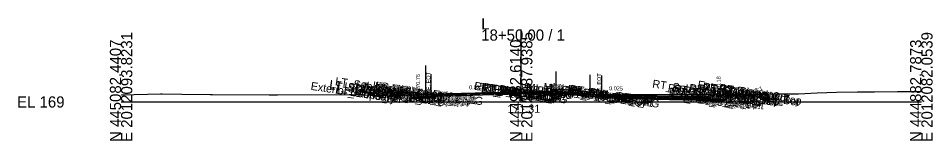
# Model space of a CAD drawing. Extents: x -26 to 4203, y -10 to 9526.
# Drawn here: x -25.7 to 202.8, y 8490.3 to 8520.9 of the extents above; entities that cross this region are included whole.
import ezdxf

# ---------------------------------------------------------------- set-up
doc = ezdxf.new("R2010")
doc.units = 0
for name, color, linetype in [('Default', 7, 'Continuous'), ('Exist CMT Pavement', 7, 'Continuous'), ('Exist Cross Section Cell', 7, 'Continuous'), ('Exist XS Center Line Elevation Label', 7, 'Continuous'), ('Exist XS Ground Line', 7, 'Continuous'), ('Prop CMT Conc Surface', 7, 'Continuous'), ('Prop CMT Concrete Structures', 7, 'Continuous'), ('Prop CMT Pvmt Course 1', 7, 'Continuous'), ('Prop CMT Pvmt Course 1 CG', 7, 'Continuous'), ('Prop CMT Pvmt Course 1 Wedge', 7, 'Continuous'), ('Prop CMT Pvmt Course 2', 7, 'Continuous'), ('Prop CMT Pvmt Course 2 Wedge', 7, 'Continuous'), ('Prop CMT Pvmt Course 3', 7, 'Continuous'), ('Prop CMT Pvmt Course 3 Wedge', 7, 'Continuous'), ('Prop CMT Pvmt Surface', 7, 'Continuous'), ('Prop CMT Pvmt Wedge Surface 1', 7, 'Continuous'), ('Prop CMT Pvmt Wedge Surface 2', 7, 'Continuous'), ('Prop CMT Pvmt Wedge Surface 3', 7, 'Continuous'), ('Prop CMT Slope Grass', 7, 'Continuous'), ('Prop CMT Subgrade Earthwork', 7, 'Continuous'), ('Prop XS Hydro Elevations', 7, 'Continuous'), ('Prop XS Label Text', 7, 'Continuous'), ('Prop XS SE Text', 7, 'Continuous'), ('Prop XS Side Slope Text', 7, 'Continuous'), ('Scratch_Level_0', 7, 'Continuous'), ('Scratch_Level_3', 7, 'Continuous')]:
    doc.layers.add(name, color=color, linetype=linetype)

msp = doc.modelspace()

# ---------------------------------------------------------------- linework, layer by layer
at = {"layer": 'Exist CMT Pavement'}
for points in [[(100, 8502.3), (98.56, 8502.3), (97.56, 8502.29), (96.44, 8502.29), (95.06, 8502.29), (93.77, 8502.28), (92.56, 8502.27), (91.48, 8502.25), (90.05, 8502.22), (88.47, 8502.17), (87.56, 8502.15), (86.74, 8502.12), (85, 8502.07), (83.11, 8502.02), (82.51, 8502), (80.47, 8501.95), (80.04, 8501.94), (78.58, 8501.94)], [(100, 8502.3), (100.07, 8502.31), (100.94, 8502.3), (102.56, 8502.28), (104.39, 8502.25), (105.05, 8502.24), (107.05, 8502.21), (107.55, 8502.2), (108, 8502.18), (110.06, 8502.13), (112.39, 8502.01), (112.57, 8502.01), (112.73, 8502), (115.08, 8501.88), (115.56, 8501.85), (117.58, 8501.76), (119.84, 8501.62), (120.06, 8501.61)]]:
    msp.add_lwpolyline(points, dxfattribs=at)
at = {"layer": 'Exist Cross Section Cell'}
for p, q in [((100, 8500), (100, 8518.13)), ((0, 8500), (100, 8500)), ((100, 8500), (200, 8500))]:
    msp.add_line(p, q, dxfattribs=at)
at = {"layer": 'Exist XS Ground Line'}
msp.add_lwpolyline([(0, 8501.79), (9.83, 8502.01), (10.23, 8502.02), (15.2, 8501.97), (22.3, 8501.85), (22.81, 8501.85), (36.99, 8501.77), (37.96, 8501.77), (38.71, 8501.77), (39.08, 8501.77), (56.97, 8501.84), (57.33, 8501.84), (57.74, 8501.85), (60.49, 8501.8), (66.86, 8501.53), (73.16, 8501.8), (74.29, 8501.83), (75.55, 8501.88), (77.39, 8501.93), (78.19, 8501.93), (80.04, 8501.94), (80.47, 8501.95), (82.51, 8502), (83.11, 8502.02), (85, 8502.07), (86.74, 8502.12), (87.56, 8502.15), (88.47, 8502.17), (90.05, 8502.22), (91.48, 8502.25), (92.56, 8502.27), (93.77, 8502.28), (95.06, 8502.29), (96.44, 8502.29), (97.56, 8502.29), (98.56, 8502.3), (100.07, 8502.31), (100.94, 8502.3), (102.56, 8502.28), (104.39, 8502.25), (105.05, 8502.24), (107.05, 8502.21), (107.55, 8502.2), (108, 8502.18), (110.06, 8502.13), (112.73, 8502), (115.08, 8501.88), (115.56, 8501.85), (117.58, 8501.76), (120.06, 8501.61), (120.63, 8501.54), (122.23, 8501.35), (123.32, 8501.37), (123.99, 8501.42), (124.59, 8501.53), (126.32, 8501.84), (138.67, 8501.92), (143.95, 8501.94), (150.41, 8501.81), (153.96, 8501.9), (157.96, 8501.91), (163.98, 8502.03), (169.33, 8502.05), (174, 8502.25), (178.79, 8502.43), (184.02, 8502.51), (188.25, 8502.55), (194.04, 8502.59), (200, 8502.6)], dxfattribs=at)
at = {"layer": 'Prop CMT Conc Surface'}
for points in [[(74.19, 8501.76), (74.19, 8502.26), (73.69, 8502.26)], [(76.19, 8501.89), (74.19, 8501.76)], [(149.33, 8501.18), (149.33, 8501.68), (149.83, 8501.68)], [(154.03, 8501.77), (159.03, 8501.87)], [(147.33, 8501.31), (149.33, 8501.18)]]:
    msp.add_lwpolyline(points, dxfattribs=at)
at = {"layer": 'Prop CMT Concrete Structures'}
for p, q in [((108.73, 8502.87), (108.72, 8502.71)), ((109.49, 8503.09), (108.73, 8502.87)), ((112.43, 8502.99), (109.49, 8503.09)), ((116.45, 8502.51), (112.43, 8502.99)), ((117.19, 8502.23), (116.45, 8502.51)), ((117.2, 8502.06), (117.19, 8502.23))]:
    msp.add_line(p, q, dxfattribs=at)
for points in [[(76.19, 8501.89), (74.19, 8501.76), (74.19, 8502.26), (73.69, 8502.26)], [(73.69, 8502.26), (73.69, 8501.25), (76.19, 8501.31)], [(76.19, 8501.31), (76.19, 8501.89)], [(108.72, 8502.71), (117.2, 8502.06)], [(147.33, 8501.31), (149.33, 8501.18), (149.33, 8501.68), (149.83, 8501.68)], [(149.83, 8501.68), (149.83, 8500.66), (147.33, 8500.72)], [(159.03, 8501.87), (154.03, 8501.77)], [(154.03, 8501.77), (154.03, 8501.44)], [(154.03, 8501.44), (159.03, 8501.54)], [(159.03, 8501.54), (159.03, 8501.87)], [(147.33, 8500.72), (147.33, 8501.31)]]:
    msp.add_lwpolyline(points, dxfattribs=at)
at = {"layer": 'Prop CMT Pvmt Course 1'}
for points in [[(76.19, 8501.89), (76.19, 8501.64)], [(100, 8502.49), (77.52, 8501.93)], [(77.52, 8501.68), (78.56, 8501.7)], [(78.56, 8501.83), (100, 8502.36)], [(78.56, 8501.7), (78.56, 8501.83)], [(100, 8502.24), (100, 8502.49)], [(100, 8502.24), (100, 8502.49)], [(100, 8502.36), (100, 8502.24), (100, 8502.24)], [(100, 8502.36), (100, 8502.24), (100, 8502.24)], [(108.72, 8502.71), (117.2, 8502.06)], [(117.19, 8501.93), (108.72, 8502.58)], [(117.2, 8502.06), (147.33, 8501.31)], [(120.06, 8501.74), (120.06, 8501.86)], [(147.33, 8501.06), (122.21, 8501.68)], [(147.33, 8501.31), (147.33, 8501.06)]]:
    msp.add_lwpolyline(points, dxfattribs=at)
at = {"layer": 'Prop CMT Pvmt Course 1 CG'}
for points in [[(76.19, 8501.31), (73.19, 8501.24), (72.85, 8500.89)], [(74.18, 8500.93), (77.52, 8501.01)], [(76.19, 8500.98), (76.19, 8501.31)], [(147.33, 8500.72), (150.33, 8500.65), (150.67, 8500.31)], [(147.33, 8500.39), (147.33, 8500.72)], [(150.67, 8500.31), (147.33, 8500.39)]]:
    msp.add_lwpolyline(points, dxfattribs=at)
at = {"layer": 'Prop CMT Pvmt Course 1 Wedge'}
for points in [[(108.72, 8502.46), (77.8, 8501.68)], [(100, 8502.31), (98.56, 8502.3), (97.56, 8502.29), (97.05, 8502.29)], [(97.05, 8502.29), (97.56, 8502.3)], [(97.56, 8502.3), (98.56, 8502.33), (100, 8502.36)], [(100, 8502.36), (100, 8502.31)], [(100, 8502.31), (100, 8502.36)], [(117.2, 8501.93), (117.58, 8501.92), (120.06, 8501.86)], [(120.06, 8501.74), (117.58, 8501.8), (117.2, 8501.81)], [(120.06, 8501.86), (120.06, 8501.74)]]:
    msp.add_lwpolyline(points, dxfattribs=at)
at = {"layer": 'Prop CMT Pvmt Course 2'}
for points in [[(78.56, 8501.7), (76.19, 8501.64)], [(76.19, 8501.64), (76.19, 8501.31)], [(78.56, 8501.37), (78.56, 8501.7)], [(120.06, 8501.4), (120.06, 8501.74)], [(122.21, 8501.68), (147.33, 8501.06)], [(76.19, 8501.31), (78.56, 8501.37)], [(147.33, 8500.72), (120.06, 8501.4)], [(147.33, 8501.06), (147.33, 8500.72)]]:
    msp.add_lwpolyline(points, dxfattribs=at)
at = {"layer": 'Prop CMT Pvmt Course 2 Wedge'}
for points in [[(108.72, 8502.46), (117.19, 8501.81)], [(120.06, 8501.61), (119.84, 8501.62), (117.58, 8501.76), (115.71, 8501.85)], [(117.2, 8501.81), (117.58, 8501.8)], [(117.58, 8501.8), (119.84, 8501.74), (120.06, 8501.74), (120.63, 8501.72), (122.21, 8501.68)], [(120.06, 8501.74), (120.06, 8501.4)]]:
    msp.add_lwpolyline(points, dxfattribs=at)
at = {"layer": 'Prop CMT Pvmt Course 3'}
for points in [[(78.56, 8501.37), (76.19, 8501.31)], [(76.19, 8501.31), (76.19, 8500.98)], [(76.19, 8500.98), (78.56, 8501.04)], [(78.56, 8501.04), (78.56, 8501.37)], [(120.06, 8501.4), (147.33, 8500.72)], [(120.06, 8501.07), (120.06, 8501.4)], [(147.33, 8500.39), (120.06, 8501.07)], [(147.33, 8500.72), (147.33, 8500.39)]]:
    msp.add_lwpolyline(points, dxfattribs=at)
at = {"layer": 'Prop CMT Pvmt Course 3 Wedge'}
msp.add_lwpolyline([(120.06, 8501.4), (120.06, 8501.4)], dxfattribs=at)
msp.add_lwpolyline([(120.06, 8501.4), (120.06, 8501.4)], dxfattribs=at)
msp.add_lwpolyline([(120.06, 8501.4), (120.06, 8501.4)], dxfattribs=at)
at = {"layer": 'Prop CMT Pvmt Surface'}
for points in [[(100, 8502.49), (76.19, 8501.89)], [(108.72, 8502.71), (100, 8502.49)], [(108.72, 8502.71), (117.2, 8502.06)], [(117.2, 8502.06), (147.33, 8501.31)]]:
    msp.add_lwpolyline(points, dxfattribs=at)
at = {"layer": 'Prop CMT Pvmt Wedge Surface 1'}
for points in [[(76.19, 8501.64), (76.19, 8501.89)], [(78.56, 8501.7), (77.52, 8501.68)], [(108.72, 8502.58), (78.56, 8501.83)], [(100, 8502.36), (78.56, 8501.83)], [(78.56, 8501.83), (78.56, 8501.7)], [(108.72, 8502.58), (117.19, 8501.93)], [(117.2, 8501.93), (120.06, 8501.86)], [(120.06, 8501.86), (120.06, 8501.74)], [(122.21, 8501.68), (147.33, 8501.06)], [(147.33, 8501.06), (147.33, 8501.31)]]:
    msp.add_lwpolyline(points, dxfattribs=at)
at = {"layer": 'Prop CMT Pvmt Wedge Surface 2'}
for points in [[(108.72, 8502.46), (76.19, 8501.64)], [(100, 8502.24), (76.19, 8501.64)], [(76.19, 8501.64), (76.19, 8501.89)], [(108.72, 8502.46), (116.98, 8501.82)], [(117.2, 8501.81), (147.33, 8501.06)], [(147.33, 8501.06), (147.33, 8501.31)]]:
    msp.add_lwpolyline(points, dxfattribs=at)
at = {"layer": 'Prop CMT Pvmt Wedge Surface 3'}
for points in [[(76.19, 8501.31), (76.19, 8501.89)], [(100, 8501.91), (77.52, 8501.34)], [(108.72, 8502.12), (100, 8501.91)], [(108.72, 8502.12), (117.17, 8501.48)], [(117.2, 8501.48), (147.33, 8500.72)], [(147.33, 8500.72), (147.33, 8501.31)]]:
    msp.add_lwpolyline(points, dxfattribs=at)
at = {"layer": 'Prop CMT Slope Grass'}
for points in [[(73.69, 8502.26), (64.19, 8502.45), (62.03, 8501.74)], [(149.83, 8501.68), (159.33, 8501.87), (159.54, 8501.94)]]:
    msp.add_lwpolyline(points, dxfattribs=at)
at = {"layer": 'Prop CMT Subgrade Earthwork'}
msp.add_line((120.06, 8501.61), (120.06, 8501.07), dxfattribs=at)
for points in [[(76.19, 8500.98), (72.85, 8500.89), (71.43, 8502.31)], [(78.56, 8501.04), (78.58, 8501.94)], [(147.33, 8500.39), (150.67, 8500.31), (152.08, 8501.72)], [(78.56, 8501.04), (76.19, 8500.98)], [(120.06, 8501.07), (147.33, 8500.39)]]:
    msp.add_lwpolyline(points, dxfattribs=at)
at = {"layer": 'Prop XS Label Text'}
for p, q in [((77.39, 8506.93), (77.39, 8501.93)), ((120.06, 8506.61), (120.06, 8501.61))]:
    msp.add_line(p, q, dxfattribs=at)
at = {"layer": 'Scratch_Level_3'}
for p, q in [((76.19, 8501.89), (76.19, 8509.11)), ((108.72, 8502.71), (108.72, 8507.58)), ((117.2, 8502.06), (117.2, 8506.78))]:
    msp.add_line(p, q, dxfattribs=at)

# ---------------------------------------------------------------- texts
at = {"layer": 'Default'}
msp.add_text('-', height=0.0001, dxfattribs=at).set_placement((0, 8500))
at = {"layer": 'Exist Cross Section Cell'}
for s, p in [('L', (90, 8518.13)), ('18+50.00 / 1', (90, 8515.33)), ('EL 169', (-26, 8498.6))]:
    msp.add_text(s, height=2.8, dxfattribs=at).set_placement(p)
for s, p in [('N 445082.4407', (0, 8490)), ('E 2012093.8231', (2.8, 8490)), ('N 444982.6140', (100, 8490)), ('E 2012087.9385', (102.8, 8490)), ('N 444882.7873', (200, 8490)), ('E 2012082.0539', (202.8, 8490))]:
    msp.add_text(s, height=2.8, rotation=90, dxfattribs=at).set_placement(p)
at = {"layer": 'Exist XS Center Line Elevation Label'}
msp.add_text('171.31', height=2, dxfattribs=at).set_placement((96.56, 8497.31))
at = {"layer": 'Prop XS Hydro Elevations'}
for s, p in [('170.76', (74.69, 8502.76)), ('170.18', (149.83, 8502.18))]:
    msp.add_text(s, height=1, rotation=90, dxfattribs=at).set_placement(p)
at = {"layer": 'Prop XS Label Text'}
for p in [(77.29, 8502.95), (119.96, 8502.63)]:
    msp.add_text('E. EOT', height=1, rotation=90, dxfattribs=at).set_placement(p)
at = {"layer": 'Prop XS SE Text'}
for rotation, p in [(1.4321, (87, 8503.16)), (358.5681, (121.95, 8502.94))]:
    msp.add_text('0.025', height=1, rotation=rotation, dxfattribs=at).set_placement(p)
at = {"layer": 'Prop XS Side Slope Text'}
for rotation, p in [(18.4295, (62, 8502.52)), (18.4724, (158.58, 8502.41))]:
    msp.add_text('3:1', height=1, rotation=rotation, dxfattribs=at).set_placement(p)
at = {"layer": 'Scratch_Level_0'}
for s, p in [('LT_Sub_Trench_Out_DLT', (53.4, 8504.24)), ('Exterior Boundary', (47.29, 8503.05)), ('LT_SDWK_Out_Top', (51.97, 8503.55)), ('LT_SDWK_Out_Bot', (52, 8503.21)), ('LT_Slope_Fill', (53.6, 8502.11)), ('LT_CSLP_Pnt', (55.65, 8502.96)), ('18+50.00', (58.01, 8502)), ('LT_SDWK_In_Top', (58.57, 8503.21)), ('LT_SDWK_In_Bot', (58.6, 8502.87)), ('18+50.00', (59.42, 8502.42)), ('LT_CG1_Shelf_Out', (61.07, 8502.27)), ('18+50.00', (62.57, 8502.36)), ('LT_CG_Top_Face', (62.77, 8503.2)), ('LT_CG_Top_BOC', (63.28, 8503.05)), ('LT_CG_Bot_BOC', (63.32, 8502.03)), ('LT_PV_Sub_Tie_Out', (63.54, 8503.18)), ('LT_CG_Top_Gut', (63.74, 8502.55)), ('18+50.00', (64.94, 8502.31)), ('LT_PV_OEEOP_EG', (66.09, 8502.79)), ('LT_CG_Bot_IE', (67.4, 8501.85)), ('LT_PV2_OEOT', (67.65, 8502.15)), ('LT_PV3_OEOT', (67.65, 8501.81)), ('LT_PV2_OEEOP', (67.84, 8502.3)), ('LT_PV3_OEEOP', (67.84, 8501.97)), ('LT_PV1_OEOT', (68.21, 8502.31)), ('LT_PV1_OEEOP', (68.4, 8502.34)), ('18+50.00', (69.25, 8501.97)), ('RT_PV_IEEOP_EG', (88.12, 8503.08)), ('LT_PV_IEEOP_EG', (88.17, 8503.07)), ('RT_PV2_IEEOP', (89.87, 8502.75)), ('RT_PV3_IEEOP', (89.87, 8502.41)), ('LT_PV2_IEEOP', (89.92, 8502.74)), ('LT_PV3_IEEOP', (89.92, 8502.41)), ('RT_PV1_IEEOP', (90.43, 8502.79)), ('LT_PV1_IEEOP', (90.48, 8502.78)), ('PV2_PGL', (93.82, 8502.15)), ('PV1_PGL', (94.39, 8502.32)), ('MI_Face In', (99.44, 8502.68)), ('MI_Bot In', (100.41, 8502.37)), ('MI_Top In', (101.14, 8502.79)), ('18+50.00', (101.34, 8502.34)), ('MI_Crown', (105.4, 8502.84)), ('18+50.00', (106.46, 8502.7)), ('RT_PV_Sub_Tie_Out', (107.11, 8502.6)), ('MI_Face Out', (107.41, 8502.68)), ('MI_Top Out', (107.61, 8502.79)), ('MI_Bot Out', (108.4, 8502.37)), ('RT_PV_OEEOP_EG', (109.7, 8502.22)), ('18+50.00', (110.92, 8502.11)), ('RT_PV2_OEEOP', (111.44, 8502.29)), ('RT_PV3_OEEOP', (111.44, 8501.95)), ('RT_PV1_OEEOP', (112, 8502.33)), ('RT_Sub_Trench_Out_DLT', (132.67, 8503.62)), ('RT_CG_Top_Face', (136.53, 8502.58)), ('RT_CG_Top_Gut', (137.5, 8501.94)), ('RT_CG_Top_BOC', (138.04, 8502.43)), ('RT_SDWK_In_Top', (141.83, 8502.59)), ('RT_SDWK_In_Bot', (141.86, 8502.25)), ('Exterior Boundary', (143.98, 8503.39)), ('RT_SDWK_Out_Top', (145.22, 8502.93)), ('RT_SDWK_Out_Bot', (145.25, 8502.59)), ('RT_Slope_Cut', (149.37, 8502.58)), ('RT_CSLP_Pnt', (149.41, 8502.34)), ('18+50.00', (153.27, 8501.87)), ('LT_Sub_OEOP', (64.25, 8501.41)), ('LT_Sub_OEOT', (67.56, 8501.49)), ('LT_Sub_OEEOP', (67.75, 8501.65)), ('18+50.00', (69.42, 8501.74)), ('RT_Sub_OEEOP', (111.35, 8501.64)), ('RT_CG1_Shelf_Out', (136.83, 8501.66)), ('RT_CG_Bot_IE', (137.16, 8501.24)), ('RT_Sub_OEOT', (137.32, 8500.88)), ('RT_PV2_OEOT', (137.41, 8501.53)), ('RT_PV3_OEOT', (137.41, 8501.2)), ('RT_PV1_OEOT', (137.97, 8501.7)), ('RT_CG_Bot_BOC', (138.07, 8501.41)), ('RT_Sub_OEOP', (140.69, 8500.79)), ('18+50.00', (143.23, 8501.61)), ('18+50.00', (144.69, 8501.63)), ('18+50.00', (147.2, 8501.69)), ('18+50.00', (151.31, 8501.77)), ('18+50.00', (152.81, 8501.8))]:
    msp.add_text(s, height=2, rotation=351.4697, dxfattribs=at).set_placement(p)

doc.saveas('drawing.dxf')
